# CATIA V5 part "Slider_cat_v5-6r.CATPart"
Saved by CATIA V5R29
Part number: Slider
Bounding box of the stored display mesh (mm): x -10 to 10, y -69.282 to 69.282, z -70 to 10
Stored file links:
  C:\Users\CADCIM 00\Desktop\New folder (2)\c16\New folder\Slide Curve\Slider_cat_v5-6r.CATPart
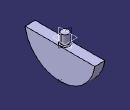
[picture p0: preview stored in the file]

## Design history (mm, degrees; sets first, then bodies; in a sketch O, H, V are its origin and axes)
Body1 (main body)
  Sketch1 on yz-plane, origin (0, 0, 0), H (0, 1, 0), V (0, 0, 1)
    arc A1 centre (0, 0) radius 70 from (-69.282, -10) to (69.282, -10) ccw
    point P1 (0, 0)
    point P2 (-69.282, -10)
    point P3 (69.282, -10)
    point P4 (0, 0)
    point P5 (-69.282, -10)
    line L1 (-69.282, -10) -> (69.282, -10)
    point P6 (69.282, -10)
    point P7 (-69.282, -10)
    reference intersected line E1 through (0, 0) direction (-1, 0) from xy-plane
    reference intersected line E3 through (0, 0) direction (0, 1) from zx-plane
    radius A1 = 70
    distance L1 P1 = 10
    coincidence: P1 V, P4 V, P6 P3, P7 A1, P2 P7, E3 P1, P2 L1, P3 L1, H P4, P2 P5, P1 H
    horizontal: L1 H, E1 H
    vertical: E3 V
    perpendicularity: E3 L1
  Pad1: profile Sketch1, direction (1, 0, 0), length 10, mirrored extent
  Point1: type OnCurve, Support edge [face of Pad1 from Sketch1.A1 | end face of Pad1], Ratio 0.5
  Sketch2 on face of Pad1 from Sketch1.L1, origin (0, 0, -10), H (1, 0, 0), V (0, 1, 0)
    circle A1 centre (0, 0) radius 7.5
    point P1 (0, 0)
    reference projected line E1 (10, 69.282) -> (10, -69.282) from edge [face of Pad1 from Sketch1.L1 | end face of Pad1]
    radius A1 = 7.5
    distance P1 E1 = 10
    coincidence: P1 H
  Pad2: profile Sketch2, direction (0, 0, 1), length 20
  Fillet1: radius 2, on edge [face of Pad1 from Sketch1.L1 | face of Pad2 from Sketch2.A1]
